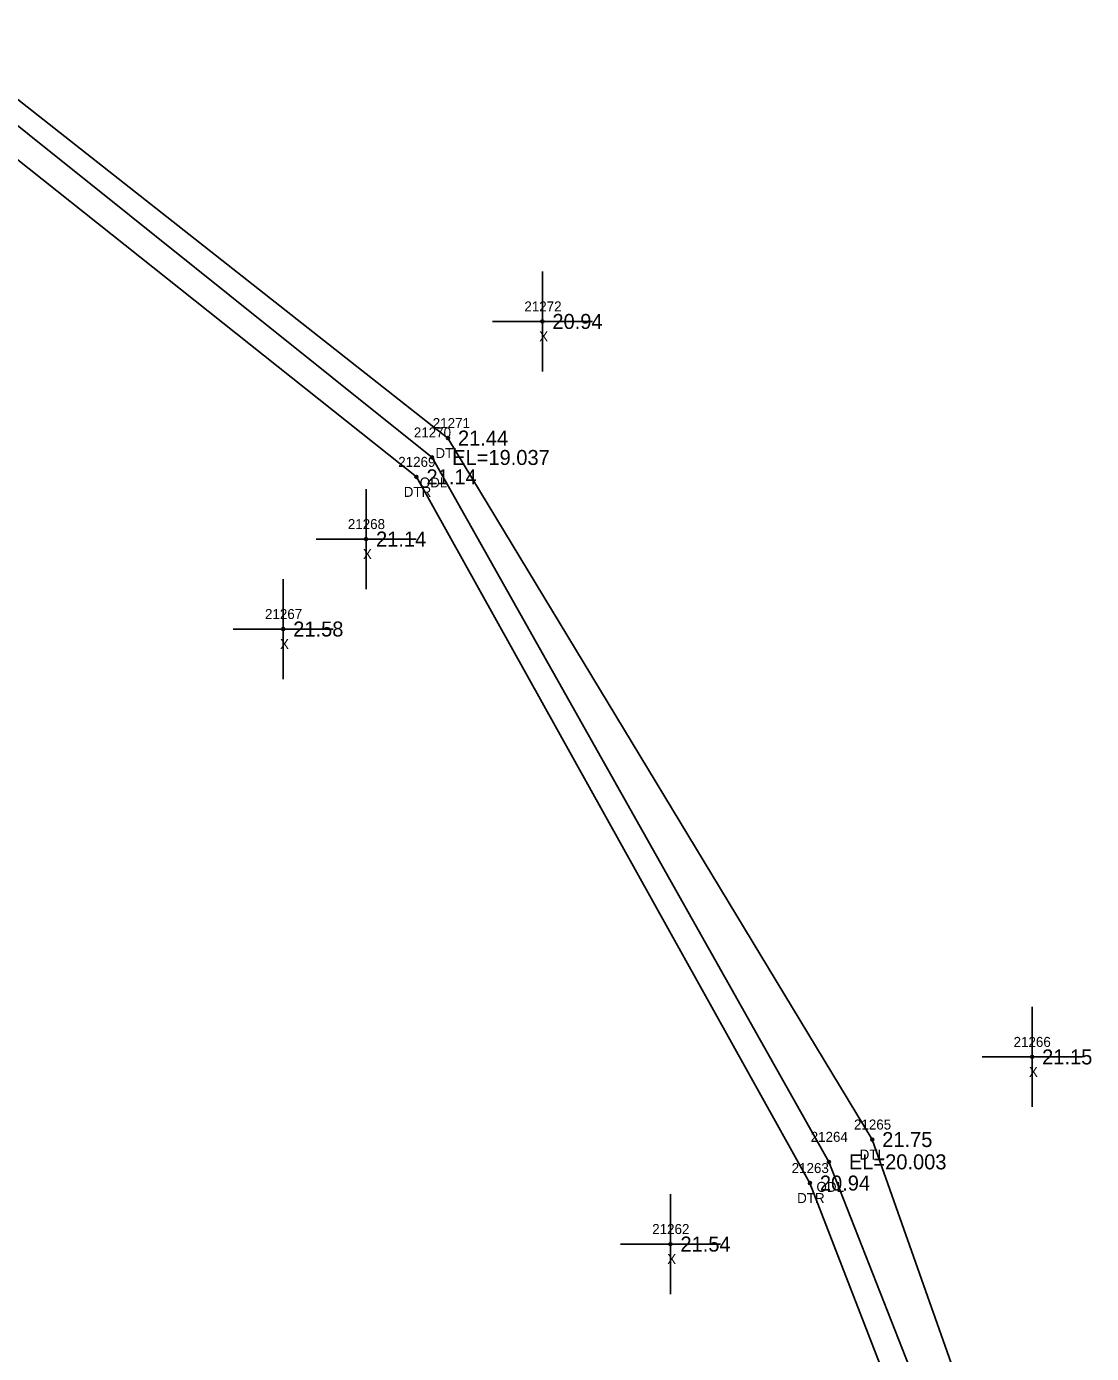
# Model space of a CAD drawing. Extents: x 2655177 to 2656219, y 761780 to 764748.
# Drawn here: x 2655579.8 to 2655686.3, y 762179.8 to 762312.5 of the extents above; entities that cross this region are included whole.
import ezdxf

# ---------------------------------------------------------------- set-up
doc = ezdxf.new("R2010")
doc.units = 0
for name, color, linetype in [('RD_EX_H2O', 7, 'Continuous'), ('RD_EX_H2O_txCode', 7, 'Continuous'), ('RD_EX_Misc', 7, 'Continuous'), ('RD_EX_Misc_txCode', 7, 'Continuous'), ('RD_EX_TX_H2O_ELEV', 7, 'Continuous'), ('RD_EX_TX_Misc_ELEV', 7, 'Continuous'), ('RD_SMD_Locator', 7, 'Continuous')]:
    doc.layers.add(name, color=color, linetype=linetype)

msp = doc.modelspace()

# ---------------------------------------------------------------- linework, layer by layer
at = {"layer": 'RD_EX_H2O'}
for points in [[(2655458.25, 762004.65), (2655489.16, 762003.6), (2655538.42, 762005.59), (2655556.05, 762013.17), (2655587.88, 762051.39), (2655643.4, 762074.04), (2655655.85, 762091.76), (2655681.86, 762140.14), (2655683.72, 762146.53), (2655664.39, 762201.23), (2655621.98, 762271.36), (2655558.86, 762321.08)], [(2655459.71, 762010.57), (2655488.92, 762008.22), (2655537.08, 762011.25), (2655554.9, 762018.55), (2655583.72, 762054.68), (2655639.44, 762078.76), (2655651.66, 762094.07), (2655673.82, 762140.27), (2655676.22, 762150.22), (2655658.16, 762196.88), (2655618.83, 762267.48), (2655556.47, 762317.07), (2655558.86, 762321.08)], [(2655456.91, 762008.75), (2655489.44, 762005.64), (2655537.92, 762008.34), (2655555.32, 762016.59), (2655585.73, 762052.79), (2655641.23, 762076.72), (2655654.31, 762091.55), (2655679.19, 762140.68), (2655679.13, 762150.47), (2655660.06, 762199), (2655620.4, 762269.42), (2655559.84, 762317.9)]]:
    msp.add_lwpolyline(points, dxfattribs=at)
at = {"layer": 'RD_EX_Misc'}
for p, q in [((2655631.42, 762278.02), (2655631.42, 762288.02)), ((2655626.42, 762283.02), (2655636.42, 762283.02)), ((2655613.79, 762256.26), (2655613.79, 762266.26)), ((2655608.79, 762261.26), (2655618.79, 762261.26)), ((2655605.51, 762247.27), (2655605.51, 762257.27)), ((2655600.51, 762252.27), (2655610.51, 762252.27)), ((2655680.38, 762204.49), (2655680.38, 762214.49)), ((2655675.38, 762209.49), (2655685.38, 762209.49)), ((2655644.22, 762185.78), (2655644.22, 762195.78)), ((2655639.22, 762190.78), (2655649.22, 762190.78))]:
    msp.add_line(p, q, dxfattribs=at)
at = {"layer": 'RD_SMD_Locator'}
for centre in [(2655631.42, 762283.02), (2655621.98, 762271.36), (2655620.4, 762269.42), (2655618.83, 762267.48), (2655613.79, 762261.26), (2655605.51, 762252.27), (2655680.38, 762209.49), (2655664.39, 762201.23), (2655660.06, 762199), (2655658.16, 762196.88), (2655644.22, 762190.78)]:
    msp.add_circle(centre, 0.15, dxfattribs=at)

# ---------------------------------------------------------------- texts
at = {"layer": 'RD_EX_H2O_txCode'}
for s, p in [('21271', (2655620.46, 762272.36)), ('21270', (2655618.57, 762271.42)), ('DTL', (2655620.73, 762269.36)), ('21269', (2655617.01, 762268.48)), ('DTR', (2655617.56, 762265.48)), ('ODL', (2655619.16, 762266.42)), ('21265', (2655662.57, 762202.23)), ('21264', (2655658.24, 762201)), ('DTL', (2655663.14, 762199.23)), ('21263', (2655656.34, 762197.88)), ('DTR', (2655656.89, 762194.88)), ('ODL', (2655658.82, 762196))]:
    msp.add_text(s, height=1, dxfattribs=at).set_placement(p)
at = {"layer": 'RD_EX_Misc_txCode'}
for s, p in [('21272', (2655629.62, 762284.02)), ('X', (2655631.1, 762281.02)), ('21268', (2655611.97, 762262.26)), ('X', (2655613.48, 762259.26)), ('21267', (2655603.69, 762253.27)), ('X', (2655605.19, 762250.27)), ('21266', (2655678.53, 762210.49)), ('X', (2655680.06, 762207.49)), ('21262', (2655642.4, 762191.78)), ('X', (2655643.9, 762188.78))]:
    msp.add_text(s, height=1, dxfattribs=at).set_placement(p)
at = {"layer": 'RD_EX_TX_H2O_ELEV'}
for s, p in [('21.44', (2655622.98, 762270.61)), ('EL=19.037', (2655622.4, 762268.67)), ('21.14', (2655619.83, 762266.73)), ('21.75', (2655665.39, 762200.48)), ('EL=20.003', (2655662.06, 762198.25)), ('20.94', (2655659.16, 762196.13))]:
    msp.add_text(s, height=1.5, dxfattribs=at).set_placement(p)
at = {"layer": 'RD_EX_TX_Misc_ELEV'}
for s, p in [('20.94', (2655632.42, 762282.27)), ('21.14', (2655614.79, 762260.51)), ('21.58', (2655606.51, 762251.52)), ('21.15', (2655681.38, 762208.74)), ('21.54', (2655645.22, 762190.03))]:
    msp.add_text(s, height=1.5, dxfattribs=at).set_placement(p)

doc.saveas('drawing.dxf')
